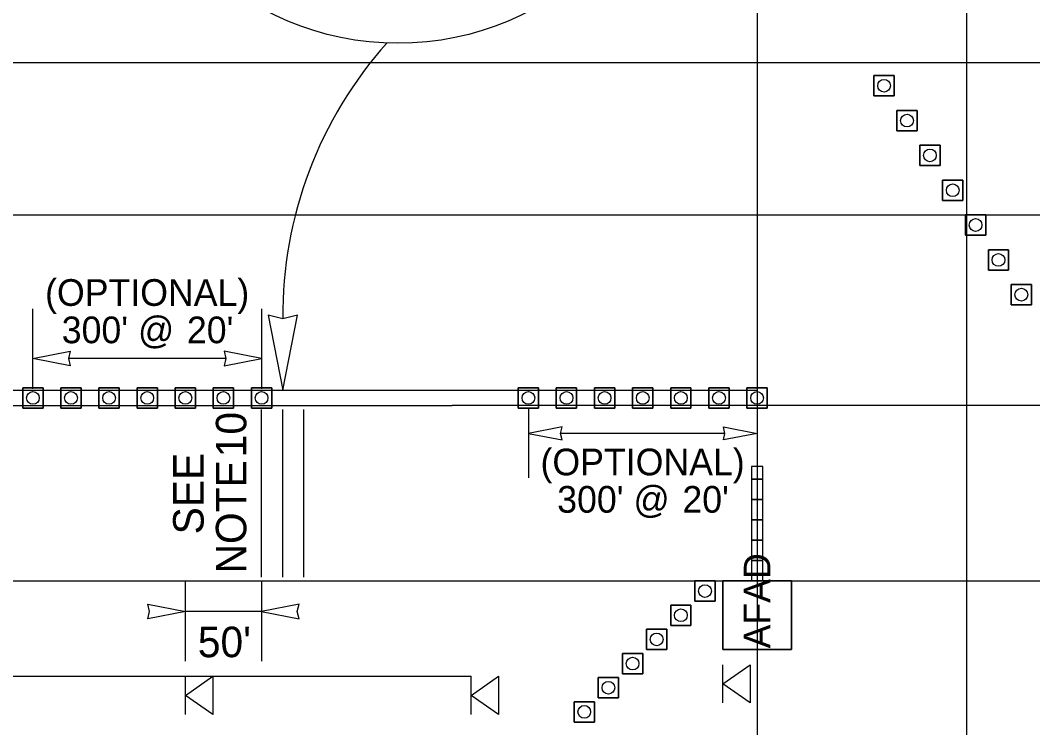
# Model space of a CAD drawing. Extents: x 99999.1 to 100095.7, y 99995 to 100010.7.
# Drawn here: x 100042.344 to 100045, y 100005.747 to 100007.603 of the extents above; entities that cross this region are included whole.
import ezdxf

# ---------------------------------------------------------------- set-up
doc = ezdxf.new("R2010")
doc.units = 0
for name, color, linetype in [('RD_ED_ShoulderPavedEdge', 7, 'Continuous'), ('RD_MK_LineDblYellowCenter', 7, 'Continuous'), ('RD_MK_LineEdgeWhite', 7, 'Continuous'), ('RD_MK_LineNoPass', 7, 'Continuous'), ('RD_MK_LineSkipCenter', 7, 'Continuous'), ('TR_WZ_AFAD', 7, 'Continuous'), ('TR_WZ_PortableSignMountBlk-Org', 7, 'Continuous'), ('TR_WZ_PortableSignMountBlk-Wht', 7, 'Continuous'), ('TR_WZ_TrafficCone', 7, 'Continuous'), ('TR_WZ_WorkZoneDetails', 7, 'Continuous'), ('TR_WZ_WorkZoneTextCurrent', 7, 'Continuous')]:
    doc.layers.add(name, color=color, linetype=linetype)

msp = doc.modelspace()

# ---------------------------------------------------------------- linework, layer by layer
at = {"layer": 'RD_ED_ShoulderPavedEdge'}
msp.add_line((100040.1076, 100007.4923), (100055.6424, 100007.4923), dxfattribs=at)
at = {"layer": 'RD_MK_LineDblYellowCenter'}
for p, q in [((100040.1282, 100006.6323), (100043.4767, 100006.6323)), ((100040.0869, 100006.5923), (100043.4767, 100006.5923))]:
    msp.add_line(p, q, dxfattribs=at)
at = {"layer": 'RD_MK_LineEdgeWhite'}
for p, q in [((100040.1076, 100007.0923), (100055.6424, 100007.0923)), ((100040.1076, 100006.1323), (100055.6424, 100006.1323))]:
    msp.add_line(p, q, dxfattribs=at)
at = {"layer": 'RD_MK_LineNoPass'}
msp.add_line((100043.4767, 100006.6323), (100044.2767, 100006.6323), dxfattribs=at)
at = {"layer": 'RD_MK_LineSkipCenter'}
msp.add_lwpolyline([(100051.15, 100006.5923), (100043.4767, 100006.5923)], dxfattribs=at)
at = {"layer": 'TR_WZ_AFAD'}
for p, q in [((100044.2916, 100006.399), (100044.2916, 100006.4323)), ((100044.2616, 100006.399), (100044.2616, 100006.3457)), ((100044.2616, 100006.399), (100044.2766, 100006.399)), ((100044.2766, 100006.399), (100044.2916, 100006.399)), ((100044.2916, 100006.3457), (100044.2916, 100006.399)), ((100044.2616, 100006.3457), (100044.2616, 100006.2923)), ((100044.2766, 100006.3457), (100044.2616, 100006.3457)), ((100044.2916, 100006.3457), (100044.2766, 100006.3457)), ((100044.2916, 100006.2923), (100044.2916, 100006.3457)), ((100044.2616, 100006.2923), (100044.2616, 100006.239)), ((100044.2616, 100006.2923), (100044.2766, 100006.2923)), ((100044.2766, 100006.2923), (100044.2916, 100006.2923)), ((100044.2916, 100006.239), (100044.2916, 100006.2923)), ((100044.2766, 100006.239), (100044.2616, 100006.239)), ((100044.2616, 100006.239), (100044.2616, 100006.1857)), ((100044.2916, 100006.239), (100044.2766, 100006.239)), ((100044.2916, 100006.1857), (100044.2916, 100006.239)), ((100044.2616, 100006.1857), (100044.2616, 100006.1323)), ((100044.1866, 100005.9523), (100044.1866, 100006.1323)), ((100044.1866, 100006.1323), (100044.3666, 100006.1323)), ((100044.27, 100006.1323), (100044.1866, 100006.1323)), ((100044.1866, 100006.1323), (100044.1866, 100005.9523)), ((100044.2616, 100006.1323), (100044.27, 100006.1323)), ((100044.27, 100006.1323), (100044.2766, 100006.1323)), ((100044.3666, 100006.1323), (100044.3666, 100005.9523)), ((100044.3666, 100005.9523), (100044.3666, 100006.1323)), ((100044.3666, 100005.9523), (100044.1866, 100005.9523)), ((100044.1866, 100005.9523), (100044.3666, 100005.9523))]:
    msp.add_line(p, q, dxfattribs=at)
for points in [[(100044.2916, 100006.4323), (100044.2616, 100006.4323), (100044.2616, 100006.399)], [(100044.2916, 100006.1323), (100044.2916, 100006.4323), (100044.2616, 100006.4323), (100044.2616, 100006.1323)], [(100044.2916, 100006.399), (100044.2766, 100006.399), (100044.2616, 100006.399)], [(100044.2616, 100006.3457), (100044.2766, 100006.3457), (100044.2916, 100006.3457)], [(100044.2916, 100006.2923), (100044.2766, 100006.2923), (100044.2616, 100006.2923)], [(100044.2616, 100006.239), (100044.2766, 100006.239), (100044.2916, 100006.239)], [(100044.2916, 100006.1857), (100044.2766, 100006.1857), (100044.2616, 100006.1857)], [(100044.2616, 100006.1857), (100044.2766, 100006.1857), (100044.2916, 100006.1857)], [(100044.2766, 100006.1323), (100044.2833, 100006.1323), (100044.2916, 100006.1323), (100044.2916, 100006.1857)], [(100044.3666, 100006.1323), (100044.2833, 100006.1323), (100044.27, 100006.1323)]]:
    msp.add_lwpolyline(points, dxfattribs=at)
at = {"layer": 'TR_WZ_PortableSignMountBlk-Org'}
for p, q in [((100042.7767, 100005.7824), (100042.7767, 100005.8824)), ((100043.5267, 100005.7824), (100043.5267, 100005.8824))]:
    msp.add_line(p, q, dxfattribs=at)
for points in [[(100042.7767, 100005.8323), (100042.8485, 100005.8824), (100042.8485, 100005.7824)], [(100043.5267, 100005.8323), (100043.5985, 100005.8824), (100043.5985, 100005.7824)]]:
    msp.add_lwpolyline(points, close=True, dxfattribs=at)
at = {"layer": 'TR_WZ_PortableSignMountBlk-Wht'}
msp.add_line((100044.1867, 100005.8123), (100044.1867, 100005.9123), dxfattribs=at)
msp.add_lwpolyline([(100044.1867, 100005.8622), (100044.2585, 100005.9123), (100044.2585, 100005.8123)], close=True, dxfattribs=at)
at = {"layer": 'TR_WZ_TrafficCone'}
for points in [[(100044.6367, 100007.4577), (100044.5834, 100007.4577), (100044.5834, 100007.4043), (100044.6367, 100007.4043), (100044.6367, 100007.4577)], [(100044.6367, 100007.4043), (100044.5834, 100007.4043), (100044.5834, 100007.4577), (100044.6367, 100007.4577), (100044.6367, 100007.4043)], [(100044.6967, 100007.3663), (100044.6434, 100007.3663), (100044.6434, 100007.313), (100044.6967, 100007.313), (100044.6967, 100007.3663)], [(100044.6967, 100007.313), (100044.6434, 100007.313), (100044.6434, 100007.3663), (100044.6967, 100007.3663), (100044.6967, 100007.313)], [(100044.7567, 100007.275), (100044.7034, 100007.275), (100044.7034, 100007.2217), (100044.7567, 100007.2217), (100044.7567, 100007.275)], [(100044.7567, 100007.2217), (100044.7034, 100007.2217), (100044.7034, 100007.275), (100044.7567, 100007.275), (100044.7567, 100007.2217)], [(100044.8167, 100007.1837), (100044.7634, 100007.1837), (100044.7634, 100007.1303), (100044.8167, 100007.1303), (100044.8167, 100007.1837)], [(100044.8167, 100007.1303), (100044.7634, 100007.1303), (100044.7634, 100007.1837), (100044.8167, 100007.1837), (100044.8167, 100007.1303)], [(100044.8234, 100007.0923), (100044.8767, 100007.0923), (100044.8767, 100007.039), (100044.8234, 100007.039), (100044.8234, 100007.0923)], [(100044.8234, 100007.039), (100044.8767, 100007.039), (100044.8767, 100007.0923), (100044.8234, 100007.0923), (100044.8234, 100007.039)], [(100044.8834, 100007.001), (100044.9367, 100007.001), (100044.9367, 100006.9477), (100044.8834, 100006.9477), (100044.8834, 100007.001)], [(100044.8834, 100006.9477), (100044.9367, 100006.9477), (100044.9367, 100007.001), (100044.8834, 100007.001), (100044.8834, 100006.9477)], [(100044.9434, 100006.9097), (100044.9967, 100006.9097), (100044.9967, 100006.8563), (100044.9434, 100006.8563), (100044.9434, 100006.9097)], [(100044.9434, 100006.8563), (100044.9967, 100006.8563), (100044.9967, 100006.9097), (100044.9434, 100006.9097), (100044.9434, 100006.8563)], [(100042.4033, 100006.639), (100042.35, 100006.639), (100042.35, 100006.5857), (100042.4033, 100006.5857), (100042.4033, 100006.639)], [(100042.4033, 100006.5857), (100042.35, 100006.5857), (100042.35, 100006.639), (100042.4033, 100006.639), (100042.4033, 100006.5857)], [(100042.5033, 100006.639), (100042.45, 100006.639), (100042.45, 100006.5857), (100042.5033, 100006.5857), (100042.5033, 100006.639)], [(100042.5033, 100006.5857), (100042.45, 100006.5857), (100042.45, 100006.639), (100042.5033, 100006.639), (100042.5033, 100006.5857)], [(100042.6033, 100006.639), (100042.55, 100006.639), (100042.55, 100006.5857), (100042.6033, 100006.5857), (100042.6033, 100006.639)], [(100042.6033, 100006.5857), (100042.55, 100006.5857), (100042.55, 100006.639), (100042.6033, 100006.639), (100042.6033, 100006.5857)], [(100042.7033, 100006.639), (100042.65, 100006.639), (100042.65, 100006.5857), (100042.7033, 100006.5857), (100042.7033, 100006.639)], [(100042.7033, 100006.5857), (100042.65, 100006.5857), (100042.65, 100006.639), (100042.7033, 100006.639), (100042.7033, 100006.5857)], [(100042.8033, 100006.639), (100042.75, 100006.639), (100042.75, 100006.5857), (100042.8033, 100006.5857), (100042.8033, 100006.639)], [(100042.8033, 100006.5857), (100042.75, 100006.5857), (100042.75, 100006.639), (100042.8033, 100006.639), (100042.8033, 100006.5857)], [(100042.9033, 100006.639), (100042.85, 100006.639), (100042.85, 100006.5857), (100042.9033, 100006.5857), (100042.9033, 100006.639)], [(100042.9033, 100006.5857), (100042.85, 100006.5857), (100042.85, 100006.639), (100042.9033, 100006.639), (100042.9033, 100006.5857)], [(100043.0033, 100006.639), (100042.95, 100006.639), (100042.95, 100006.5857), (100043.0033, 100006.5857), (100043.0033, 100006.639)], [(100043.0033, 100006.5857), (100042.95, 100006.5857), (100042.95, 100006.639), (100043.0033, 100006.639), (100043.0033, 100006.5857)], [(100043.7033, 100006.639), (100043.65, 100006.639), (100043.65, 100006.5857), (100043.7033, 100006.5857), (100043.7033, 100006.639)], [(100043.7033, 100006.5857), (100043.65, 100006.5857), (100043.65, 100006.639), (100043.7033, 100006.639), (100043.7033, 100006.5857)], [(100043.8033, 100006.639), (100043.75, 100006.639), (100043.75, 100006.5857), (100043.8033, 100006.5857), (100043.8033, 100006.639)], [(100043.8033, 100006.5857), (100043.75, 100006.5857), (100043.75, 100006.639), (100043.8033, 100006.639), (100043.8033, 100006.5857)], [(100043.9033, 100006.639), (100043.85, 100006.639), (100043.85, 100006.5857), (100043.9033, 100006.5857), (100043.9033, 100006.639)], [(100043.9033, 100006.5857), (100043.85, 100006.5857), (100043.85, 100006.639), (100043.9033, 100006.639), (100043.9033, 100006.5857)], [(100044.0033, 100006.639), (100043.95, 100006.639), (100043.95, 100006.5857), (100044.0033, 100006.5857), (100044.0033, 100006.639)], [(100044.0033, 100006.5857), (100043.95, 100006.5857), (100043.95, 100006.639), (100044.0033, 100006.639), (100044.0033, 100006.5857)], [(100044.1033, 100006.639), (100044.05, 100006.639), (100044.05, 100006.5857), (100044.1033, 100006.5857), (100044.1033, 100006.639)], [(100044.1033, 100006.5857), (100044.05, 100006.5857), (100044.05, 100006.639), (100044.1033, 100006.639), (100044.1033, 100006.5857)], [(100044.2033, 100006.639), (100044.15, 100006.639), (100044.15, 100006.5857), (100044.2033, 100006.5857), (100044.2033, 100006.639)], [(100044.2033, 100006.5857), (100044.15, 100006.5857), (100044.15, 100006.639), (100044.2033, 100006.639), (100044.2033, 100006.5857)], [(100044.3033, 100006.639), (100044.25, 100006.639), (100044.25, 100006.5857), (100044.3033, 100006.5857), (100044.3033, 100006.639)], [(100044.3033, 100006.5857), (100044.25, 100006.5857), (100044.25, 100006.639), (100044.3033, 100006.639), (100044.3033, 100006.5857)], [(100044.1133, 100006.1323), (100044.1667, 100006.1323), (100044.1667, 100006.079), (100044.1133, 100006.079), (100044.1133, 100006.1323)], [(100044.1133, 100006.079), (100044.1667, 100006.079), (100044.1667, 100006.1323), (100044.1133, 100006.1323), (100044.1133, 100006.079)], [(100044.05, 100006.069), (100044.1033, 100006.069), (100044.1033, 100006.0157), (100044.05, 100006.0157), (100044.05, 100006.069)], [(100044.05, 100006.0157), (100044.1033, 100006.0157), (100044.1033, 100006.069), (100044.05, 100006.069), (100044.05, 100006.0157)], [(100043.9867, 100006.0057), (100044.04, 100006.0057), (100044.04, 100005.9523), (100043.9867, 100005.9523), (100043.9867, 100006.0057)], [(100043.9867, 100005.9523), (100044.04, 100005.9523), (100044.04, 100006.0057), (100043.9867, 100006.0057), (100043.9867, 100005.9523)], [(100043.9767, 100005.9423), (100043.9233, 100005.9423), (100043.9233, 100005.889), (100043.9767, 100005.889), (100043.9767, 100005.9423)], [(100043.9767, 100005.889), (100043.9233, 100005.889), (100043.9233, 100005.9423), (100043.9767, 100005.9423), (100043.9767, 100005.889)], [(100043.9133, 100005.879), (100043.86, 100005.879), (100043.86, 100005.8257), (100043.9133, 100005.8257), (100043.9133, 100005.879)], [(100043.9133, 100005.8257), (100043.86, 100005.8257), (100043.86, 100005.879), (100043.9133, 100005.879), (100043.9133, 100005.8257)], [(100043.85, 100005.8157), (100043.7967, 100005.8157), (100043.7967, 100005.7623), (100043.85, 100005.7623), (100043.85, 100005.8157)], [(100043.85, 100005.7623), (100043.7967, 100005.7623), (100043.7967, 100005.8157), (100043.85, 100005.8157), (100043.85, 100005.7623)]]:
    msp.add_lwpolyline(points, dxfattribs=at)
for centre in [(100044.61, 100007.431), (100044.67, 100007.3397), (100044.73, 100007.2483), (100044.79, 100007.157), (100044.85, 100007.0657), (100044.91, 100006.9743), (100044.97, 100006.883), (100042.3767, 100006.6123), (100042.4767, 100006.6123), (100042.5767, 100006.6123), (100042.6767, 100006.6123), (100042.7767, 100006.6123), (100042.8767, 100006.6123), (100042.9767, 100006.6123), (100043.6767, 100006.6123), (100043.7767, 100006.6123), (100043.8767, 100006.6123), (100043.9767, 100006.6123), (100044.0767, 100006.6123), (100044.1767, 100006.6123), (100044.2767, 100006.6123), (100044.14, 100006.1057), (100044.0767, 100006.0423), (100044.0133, 100005.979), (100043.95, 100005.9157), (100043.8867, 100005.8523), (100043.8233, 100005.789)]:
    msp.add_circle(centre, 0.0167, dxfattribs=at)
at = {"layer": 'TR_WZ_WorkZoneDetails'}
for p, q in [((100044.2767, 100008.7991), (100044.2767, 100005.4923)), ((100044.8267, 100005.4923), (100044.8267, 100007.7323)), ((100042.3767, 100006.6357), (100042.3767, 100006.8457)), ((100042.9767, 100006.8457), (100042.9767, 100006.6357)), ((100042.8829, 100006.7157), (100042.4704, 100006.7157)), ((100042.9767, 100006.1423), (100042.9767, 100006.5823)), ((100043.0323, 100006.1423), (100043.0323, 100006.5823)), ((100043.0872, 100006.1423), (100043.0872, 100006.5823)), ((100043.6767, 100006.5857), (100043.6767, 100006.4023)), ((100044.1923, 100006.5193), (100043.761, 100006.5193)), ((100042.7767, 100005.9223), (100042.7767, 100006.1323)), ((100042.9767, 100006.1323), (100042.9767, 100005.9223)), ((100042.9767, 100006.0523), (100042.7767, 100006.0523)), ((100040.5267, 100005.8824), (100043.5267, 100005.8824))]:
    msp.add_line(p, q, dxfattribs=at)
for points in [[(100043.0323, 100006.6323), (100043.0708, 100006.8289), (100043.0323, 100006.8198), (100042.9937, 100006.8289)], [(100042.3767, 100006.7157), (100042.4749, 100006.7349), (100042.4704, 100006.7157), (100042.4749, 100006.6964)], [(100042.9767, 100006.7157), (100042.8784, 100006.7349), (100042.8829, 100006.7157), (100042.8784, 100006.6964)], [(100043.6767, 100006.5193), (100043.7651, 100006.502), (100043.761, 100006.5193), (100043.7651, 100006.5367)], [(100044.2767, 100006.5193), (100044.1882, 100006.502), (100044.1923, 100006.5193), (100044.1882, 100006.5367)], [(100042.7767, 100006.0523), (100042.6784, 100006.0331), (100042.6829, 100006.0523), (100042.6784, 100006.0716)], [(100042.9767, 100006.0523), (100043.0749, 100006.0331), (100043.0704, 100006.0523), (100043.0749, 100006.0716)]]:
    msp.add_lwpolyline(points, close=True, dxfattribs=at)
msp.add_circle((100043.3346, 100008.2843), 0.742, dxfattribs=at)
msp.add_arc((100044.1081, 100006.8268), 1.0759, 138.2705, 180.3733, dxfattribs=at)

# ---------------------------------------------------------------- texts
at = {"layer": 'TR_WZ_AFAD'}
msp.add_text('AFAD', height=0.07, rotation=90, dxfattribs=at).set_placement((100044.3116, 100005.9553))
at = {"layer": 'TR_WZ_WorkZoneDetails'}
for s, p in [('10', (100042.9367, 100006.4566)), ('SEE', (100042.8247, 100006.2544)), ('NOTE', (100042.9367, 100006.1518))]:
    msp.add_text(s, height=0.08, rotation=90, dxfattribs=at).set_placement(p)
at = {"layer": 'TR_WZ_WorkZoneTextCurrent'}
for s, height, p in [('(OPTIONAL)', 0.07, (100042.4087, 100006.8537)), ("300' @", 0.07, (100042.4524, 100006.7557)), ("20'", 0.07, (100042.7808, 100006.7557)), ('(OPTIONAL)', 0.07, (100043.7085, 100006.4093)), ("300' @", 0.07, (100043.7523, 100006.3113)), ("20'", 0.07, (100044.0807, 100006.3113)), ("50'", 0.08, (100042.8094, 100005.9323))]:
    msp.add_text(s, height=height, dxfattribs=at).set_placement(p)

doc.saveas('drawing.dxf')
